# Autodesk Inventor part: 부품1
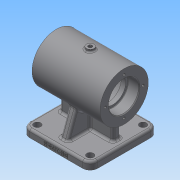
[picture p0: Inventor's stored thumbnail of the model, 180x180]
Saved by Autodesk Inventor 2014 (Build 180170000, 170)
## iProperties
Created: 2019-06
Part Number: 부품1
Material: 일반
Document SubType Name: Modeling
Designer: net
Density: 1 g/cm^3
Appearance: 기본값
Mass: 225.527 g
Surface Area: 626.694 cm^2
Volume: 225.527 cm^3
Author: net
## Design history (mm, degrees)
sketch "스케치1"
  geometry: L1 (45, 0)-(-45, 0); L2 (45, 20)-(30, 20); L3 (30, 20)-(30, 17); L4 (30, 17)-(24, 17); L5 (24, 17)-(24, 25); L6 (24, 25)-(-24, 25); L7 (-24, 25)-(-24, 17); L8 (-24, 17)-(-30, 17); L9 (-30, 17)-(-30, 20); L10 (-30, 20)-(-45, 20); L11 (-45, 20)-(-45, 32); L12 (-45, 32)-(45, 32); L13 (45, 32)-(45, 20); 4 further points
  constraints: 26 end point, 10 parallel, 3 midpoint, 2 vertical alignment, 1 coincident, 1 collinear, 1 horizontal, 1 perpendicular
  dimensions: "d0" = 90 distance of L1.start L1.end; "d1" = 48 distance of L5.end L6.end; "d2" = 15 distance of L2.start L2.end; "d3" = 15 distance of L9.end L10.end; "d4" = 50 diameter of L6 L1; "d5" = 34 diameter of L4 L1; "d6" = 40 diameter of L2 L1; "d7" = 34 diameter of L8 L1; "d8" = 40 diameter of L10 L1; "d9" = 64 diameter of L12 L1; "d10" = 6 distance of L3.end L4.end
revolve "회전1" sketch "스케치1" stored, may be unused: angle "d11" = 90 deg
node "작업 평면1"
sketch "스케치2"
  geometry: L1 (-45, 45)-(45, 45); L2 (45, 45)-(45, -45); L3 (45, -45)-(-45, -45); L4 (-45, -45)-(-45, 45); 3 further points
  constraints: 8 end point, 2 midpoint, 2 parallel, 1 horizontal, 1 horizontal alignment, 1 perpendicular, 1 vertical alignment
  dimensions: "d13" = 90 distance of L2.end L3.end; "d14" = 90 distance of L1.end L2.end
extrude "돌출1" join sketch "스케치2" distance "d15" = 10; taper "d16" = 0 deg
sketch "스케치3"
  geometry: L1 (-45, 45)-(-45, -45) reference; L2 (-35, 5)-(35, 5); L3 (35, 5)-(35, -5); L4 (35, -5)-(-35, -5); L5 (-35, -5)-(-35, 5); 2 further points
  constraints: 8 end point, 2 parallel, 1 horizontal, 1 horizontal alignment, 1 midpoint, 1 perpendicular
  dimensions: "d17" = 70 distance of L3.end L4.end; "d18" = 10 distance of L2.end L3.end; "d19" = 10 distance between parallel lines of L5 L1
extrude "돌출2" join sketch "스케치3" stored distance "d20" = 10; taper "d21" = 0 deg
sketch "스케치4"
  geometry: L1 (45, -55)-(45, -65) reference; L2 (45, -65)-(-45, -65) reference; L3 (-45, -65)-(-45, -55) reference; L4 (-45, -55)-(-5, -55) reference; L5 (-5, -55)-(-5, -31.607) reference; L6 (5, -31.607)-(5, -55) reference; L7 (5, -55)-(45, -55) reference; L8 (-23.058, -22.189)-(-35, -55); C1 r 25 at (0, 0) reference; A1 r 32 centre (0, 0) between (5, -31.607) and (-5, -31.607) reference; 1 further point
  constraints: 2 end point, 1 point on circle, 1 point on line
  dimensions: "d22" = 110 deg angle of L4 L8; "d23" = 10 distance from line of L3 L8.end
feature "리브1" sketch "스케치4" dims "d24" = 1, "d25" = 10, "d26" = 0, "d27" = 0, "d28" = 1, "d29" = 1
fillet "모깎기1" dims "d30" = 10
fillet "모깎기2" dims "d31" = 3
sketch "스케치5"
  geometry: C1 r 4.5 at (-35, 35); C2 r 4.5 at (35, 35); C3 r 4.5 at (-35, -35); C4 r 4.5 at (35, -35); A1 r 7 centre (-35, -35) between (-42, -35) and (-35, -42) reference; A2 r 7 centre (35, -35) between (35, -42) and (42, -35) reference; A3 r 7 centre (35, 35) between (42, 35) and (35, 42) reference; A4 r 7 centre (-35, 35) between (-35, 42) and (-42, 35) reference; 1 further point
  constraints: 4 centre point, 4 coincident
  dimensions: "d32" = 9 diameter of C1; "d33" = 9 diameter of C2; "d34" = 9 diameter of C3; "d35" = 9 diameter of C4
extrude "돌출3" cut sketch "스케치5" stored distance "d36" = 10; taper "d37" = 0 deg
sketch "스케치6" dims "d38" = 50
  geometry: C1 r 20 at (0, 0) reference; 2 further points
  constraints: 2 horizontal alignment, 1 coincident, 2 other
hole "구멍1" sketch "스케치6" at (25, 0) diameter "d39" = 3.242; stored, may be unused: countersink angle "d43" = 90 deg, drill point angle "d45" = 118 deg; dims "d40" = 7, "d41" = 4, "d42" = 2, "d44" = 9
sketch "스케치7" dims "d49" = 50
  geometry: C1 r 20 at (0, 0) reference; 2 further points
  constraints: 2 horizontal alignment, 1 coincident, 2 other
hole "구멍2" sketch "스케치7" at (-25, 0) diameter "d50" = 3.242; stored, may be unused: countersink angle "d54" = 90 deg, drill point angle "d56" = 118 deg; dims "d51" = 7, "d52" = 4, "d53" = 2, "d55" = 9
sketch "스케치8"
  geometry: L1 (-42, -55)-(-35, -55) reference; L2 (-35, -55)-(-23.058, -22.189) reference; L3 (23.058, -22.189)-(35, -55) reference; L4 (35, -55)-(42, -55) reference; L5 (45, -58)-(45, -65) reference; L6 (45, -65)-(-45, -65) reference; L7 (-45, -65)-(-45, -58) reference; L8 (0, 32)-(0, 35); C1 r 25 at (0, 0) reference; A1 r 3 centre (-42, -58) between (-42, -55) and (-45, -58) reference; A2 r 32 centre (0, 0) between (23.058, -22.189) and (-23.058, -22.189) reference; A3 r 3 centre (42, -58) between (45, -58) and (42, -55) reference; 1 further point
  constraints: 2 end point, 1 parallel, 1 point on circle
  dimensions: "d60" = 100 distance from line of L6 L8.end
  node "절단 모서리 투영2"
node "작업 평면2"
sketch "스케치9"
  geometry: C1 r 5 at (0, 0); 1 further point
  constraints: 1 centre point, 1 coincident
  dimensions: "d61" = 10 diameter of C1
extrude "돌출4" join sketch "스케치9" stored distance "d62" = 10; taper "d63" = 0 deg
sketch "스케치10"
  geometry: C1 r 5 at (0, 0) reference; 1 further point
  constraints: 1 coincident
hole "구멍3" sketch "스케치10" at (0, 0) diameter "d64" = 4.917; stored, may be unused: countersink angle "d68" = 90 deg, drill point angle "d70" = 118 deg; dims "d65" = 40, "d66" = 4, "d67" = 2, "d69" = 9
sketch "스케치11"
  geometry: L1 (45, -35)-(45, 35) reference; L2 (-22, 40)-(22, 40); L3 (25, 37)-(25, 35); L4 (35, 25)-(37, 25); L5 (40, 22)-(40, -22); L6 (37, -25)-(35, -25); L7 (25, -35)-(25, -37); L8 (22, -40)-(-22, -40); L9 (-25, -37)-(-25, -35); L10 (-35, -25)-(-37, -25); L11 (-40, -22)-(-40, 22); L12 (-37, 25)-(-35, 25); L13 (-25, 35)-(-25, 37); L14 (0, 40)-(0, -40); L15 (-40, 0)-(40, 0); C1 r 4.5 at (-35, -35) reference; A1 r 10 centre (35, 35) between (45, 35) and (35, 45) reference; A2 r 10 centre (-35, 35) between (-35, 45) and (-45, 35) reference; A3 r 10 centre (-35, 35) between (-35, 25) and (-25, 35); A4 r 10 centre (35, 35) between (25, 35) and (35, 25); A5 r 10 centre (35, -35) between (35, -25) and (25, -35); A6 r 10 centre (-35, -35) between (-25, -35) and (-35, -25); A7 r 3 centre (-22, 37) between (-22, 40) and (-25, 37); A8 r 3 centre (-37, 22) between (-37, 25) and (-40, 22); A9 r 3 centre (-37, -22) between (-40, -22) and (-37, -25); A10 r 3 centre (-22, -37) between (-25, -37) and (-22, -40); A11 r 3 centre (22, -37) between (22, -40) and (25, -37); A12 r 3 centre (37, -22) between (37, -25) and (40, -22); A13 r 3 centre (37, 22) between (40, 22) and (37, 25); A14 r 3 centre (22, 37) between (25, 37) and (22, 40); 2 further points
  constraints: 28 end point, 24 point on circle, 24 tangent, 12 centre point, 10 equal radius, 8 parallel, 6 midpoint, 5 perpendicular, 4 coincident, 2 horizontal alignment, 2 vertical alignment, 1 collinear
  dimensions: "d71" = 80 distance between parallel lines of L5 L11; "d72" = 80 distance between parallel lines of L8 L2; "d73" = 10 radius of A3; "d74" = 3 radius of A7
extrude "돌출5" cut sketch "스케치11" distance "d75" = 5; taper "d76" = 0 deg
sketch "스케치12"
  geometry: L1 (70, 0)-(0, 0) reference; L2 (-10, 7)-(-10, 0) reference; 2 further points
  constraints: 1 other
  dimensions: "d77" = 4 distance from line of L1 point (35, 4); "d78" = 45 distance from line of L2 point (35, 4)
feature "엠보싱1" sketch "스케치12" dims "d13" = 90, "d14" = 90, "d79" = 0.5, "d80" = 0
fillet "모깎기3" dims "d81" = 3
fillet "모깎기4" dims "d82" = 3
chamfer "모따기1" distance "d83" = 1; stored, may be unused: second distance "d84" = 2, angle "d85" = 45 deg
chamfer "모따기2" distance "d86" = 1; stored, may be unused: second distance "d87" = 2, angle "d88" = 45 deg
fillet "모깎기5" dims "d89" = 2
fillet "모깎기6" dims "d90" = 0.6
node "솔리드1"
mirror "대칭1"
pattern_circular "원형 패턴1" dims angle "d47" = 360 deg
pattern_circular "원형 패턴2" dims angle "d58" = 360 deg
node "절단 모서리 투영1"
other parameters: "d12" = -65
